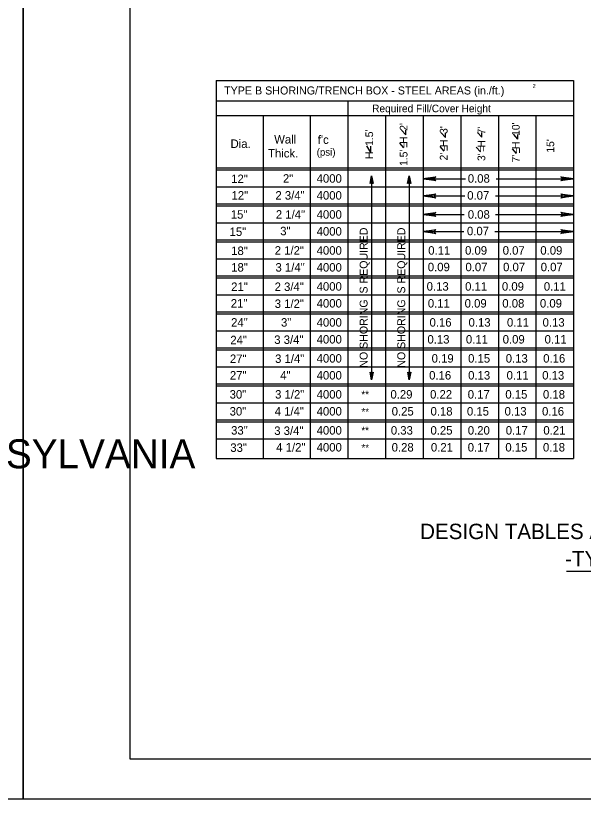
# Model space of a CAD drawing. Extents: x -22562 to -18409, y 3991 to 7171.
# Drawn here: x -20387.7 to -20175.1, y 3991.4 to 4284.9 of the extents above; entities that cross this region are included whole.
import ezdxf

# ---------------------------------------------------------------- set-up
doc = ezdxf.new("R2010")
doc.units = 0
for name, color, linetype in [('1', 7, 'Continuous'), ('2', 7, 'Continuous'), ('3', 7, 'Continuous'), ('4', 7, 'Continuous'), ('PLT-BNDY', 7, 'Continuous')]:
    doc.layers.add(name, color=color, linetype=linetype)

msp = doc.modelspace()

# ---------------------------------------------------------------- linework, layer by layer
at = {"layer": '1'}
for p, q in [((-20312.63, 4260.6), (-20312.63, 4119.05)), ((-20178.71, 4260.6), (-20178.71, 4119.05)), ((-20263.29, 4253.03), (-20263.29, 4119.05)), ((-20312.63, 4247.53), (-20178.71, 4247.53)), ((-20295.01, 4247.53), (-20295.01, 4119.05)), ((-20277.39, 4247.53), (-20277.39, 4119.05)), ((-20249.19, 4247.53), (-20249.19, 4119.05)), ((-20235.1, 4247.53), (-20235.1, 4119.05)), ((-20221, 4247.53), (-20221, 4119.05)), ((-20206.9, 4247.53), (-20206.9, 4119.05)), ((-20192.8, 4247.53), (-20192.8, 4119.05)), ((-20241.61, 4240.25), (-20243.17, 4242.01)), ((-20241.61, 4240.25), (-20241.61, 4242)), ((-20226.72, 4239.3), (-20228.28, 4241.07)), ((-20226.72, 4239.3), (-20226.72, 4241.06)), ((-20213.14, 4239.36), (-20214.7, 4241.13)), ((-20213.14, 4239.36), (-20213.14, 4241.12)), ((-20199.59, 4238.61), (-20201.15, 4240.38)), ((-20199.59, 4238.61), (-20199.59, 4240.37)), ((-20178.71, 4239.8), (-20178.71, 4119.27)), ((-20254.61, 4233.68), (-20256.17, 4236.11)), ((-20254.61, 4233.68), (-20254.61, 4236.09)), ((-20242.26, 4235.44), (-20243.83, 4237.21)), ((-20227.17, 4234.16), (-20228.73, 4235.93)), ((-20213.6, 4233.95), (-20215.16, 4235.71)), ((-20200.04, 4233.25), (-20201.61, 4235.02)), ((-20312.63, 4227.9), (-20178.71, 4227.9)), ((-20312.63, 4227.11), (-20178.71, 4227.11)), ((-20235.1, 4223.83), (-20219.22, 4223.83)), ((-20207.76, 4223.83), (-20178.71, 4223.83)), ((-20312.63, 4220.77), (-20178.71, 4220.77)), ((-20312.63, 4220.77), (-20178.71, 4220.77)), ((-20235.1, 4217.37), (-20219.43, 4217.37)), ((-20207.97, 4217.37), (-20178.71, 4217.37)), ((-20312.63, 4214.42), (-20178.71, 4214.42)), ((-20312.63, 4214.42), (-20178.71, 4214.42)), ((-20312.63, 4213.63), (-20178.71, 4213.63)), ((-20235.1, 4210.48), (-20219.64, 4210.48)), ((-20207.97, 4210.48), (-20178.71, 4210.48)), ((-20312.63, 4207.29), (-20178.71, 4207.29)), ((-20312.63, 4207.29), (-20178.71, 4207.29)), ((-20235.1, 4204.02), (-20219.85, 4204.02)), ((-20208.18, 4204.02), (-20178.71, 4204.02)), ((-20312.63, 4200.94), (-20178.71, 4200.94)), ((-20312.63, 4200.94), (-20178.71, 4200.94)), ((-20312.63, 4200.15), (-20178.71, 4200.15)), ((-20312.63, 4193.81), (-20178.71, 4193.81)), ((-20312.63, 4193.81), (-20178.71, 4193.81)), ((-20312.63, 4187.46), (-20178.71, 4187.46)), ((-20312.63, 4187.46), (-20178.71, 4187.46)), ((-20312.63, 4186.67), (-20178.71, 4186.67)), ((-20312.63, 4180.33), (-20178.71, 4180.33)), ((-20312.63, 4180.33), (-20178.71, 4180.33)), ((-20312.63, 4173.98), (-20178.71, 4173.98)), ((-20312.63, 4173.98), (-20178.71, 4173.98)), ((-20312.63, 4173.19), (-20178.71, 4173.19)), ((-20312.63, 4166.85), (-20178.71, 4166.85)), ((-20312.63, 4166.85), (-20178.71, 4166.85)), ((-20312.63, 4160.5), (-20178.71, 4160.5)), ((-20312.63, 4160.5), (-20178.71, 4160.5)), ((-20312.63, 4159.71), (-20178.71, 4159.71)), ((-20312.63, 4153.37), (-20178.71, 4153.37)), ((-20312.63, 4153.37), (-20178.71, 4153.37)), ((-20312.63, 4147.02), (-20178.71, 4147.02)), ((-20312.63, 4147.02), (-20178.71, 4147.02)), ((-20312.63, 4146.23), (-20178.71, 4146.23)), ((-20312.63, 4139.89), (-20178.71, 4139.89)), ((-20312.63, 4139.89), (-20178.71, 4139.89)), ((-20312.63, 4133.54), (-20178.71, 4133.54)), ((-20312.63, 4133.54), (-20178.71, 4133.54)), ((-20312.63, 4132.75), (-20178.71, 4132.75)), ((-20312.63, 4126.41), (-20178.71, 4126.41)), ((-20312.63, 4126.41), (-20178.71, 4126.41)), ((-20312.63, 4119.05), (-20178.71, 4119.05))]:
    msp.add_line(p, q, dxfattribs=at)
for points in [[(-20230.57, 4223.26), (-20230.74, 4223.59), (-20235.1, 4223.83), (-20230.57, 4223.26), (-20230.34, 4223.06), (-20235.1, 4223.83), (-20230.74, 4224.05), (-20230.58, 4224.37), (-20235.1, 4223.83), (-20230.34, 4224.59), (-20230.58, 4224.37)], [(-20183.23, 4224.4), (-20183.07, 4224.07), (-20178.71, 4223.83), (-20183.23, 4224.4), (-20183.47, 4224.6), (-20178.71, 4223.83), (-20183.06, 4223.62), (-20183.22, 4223.29), (-20178.71, 4223.83), (-20183.47, 4223.07), (-20183.22, 4223.29)], [(-20230.57, 4216.8), (-20230.74, 4217.13), (-20235.1, 4217.37), (-20230.57, 4216.8), (-20230.34, 4216.6), (-20235.1, 4217.37), (-20230.74, 4217.58), (-20230.58, 4217.9), (-20235.1, 4217.37), (-20230.34, 4218.12), (-20230.58, 4217.9)], [(-20183.23, 4217.93), (-20183.07, 4217.61), (-20178.71, 4217.37), (-20183.23, 4217.93), (-20183.47, 4218.13), (-20178.71, 4217.37), (-20183.06, 4217.15), (-20183.22, 4216.83), (-20178.71, 4217.37), (-20183.47, 4216.61), (-20183.22, 4216.83)], [(-20230.57, 4209.92), (-20230.74, 4210.24), (-20235.1, 4210.48), (-20230.57, 4209.92), (-20230.34, 4209.72), (-20235.1, 4210.48), (-20230.74, 4210.7), (-20230.58, 4211.02), (-20235.1, 4210.48), (-20230.34, 4211.24), (-20230.58, 4211.02)], [(-20183.23, 4211.05), (-20183.07, 4210.72), (-20178.71, 4210.48), (-20183.23, 4211.05), (-20183.47, 4211.25), (-20178.71, 4210.48), (-20183.06, 4210.27), (-20183.22, 4209.95), (-20178.71, 4210.48), (-20183.47, 4209.73), (-20183.22, 4209.95)], [(-20230.57, 4203.45), (-20230.74, 4203.78), (-20235.1, 4204.02), (-20230.57, 4203.45), (-20230.34, 4203.25), (-20235.1, 4204.02), (-20230.74, 4204.23), (-20230.58, 4204.55), (-20235.1, 4204.02), (-20230.34, 4204.77), (-20230.58, 4204.55)], [(-20183.23, 4204.58), (-20183.07, 4204.26), (-20178.71, 4204.02), (-20183.23, 4204.58), (-20183.47, 4204.78), (-20178.71, 4204.02), (-20183.06, 4203.8), (-20183.22, 4203.48), (-20178.71, 4204.02), (-20183.47, 4203.26), (-20183.22, 4203.48)]]:
    msp.add_lwpolyline(points, dxfattribs=at)
at = {"layer": '2'}
for p, q in [((-20344.85, 4006.37), (-20344.85, 4570.37)), ((-20312.63, 4260.6), (-20178.71, 4260.6)), ((-20312.63, 4253.03), (-20178.71, 4253.03)), ((-20254.4, 4224.92), (-20254.4, 4148.54)), ((-20240.3, 4224.92), (-20240.3, 4148.54)), ((-20181.42, 4076.88), (-19960.99, 4076.88)), ((-19558.85, 4006.37), (-20344.85, 4006.37))]:
    msp.add_line(p, q, dxfattribs=at)
for points in [[(-20254.82, 4222.2), (-20254.58, 4222.3), (-20254.4, 4224.92), (-20254.82, 4222.2), (-20254.97, 4222.06), (-20254.4, 4224.92), (-20254.24, 4222.3), (-20253.99, 4222.21), (-20254.4, 4224.92), (-20253.84, 4222.06), (-20253.99, 4222.21)], [(-20240.73, 4222.2), (-20240.48, 4222.3), (-20240.3, 4224.92), (-20240.73, 4222.2), (-20240.87, 4222.06), (-20240.3, 4224.92), (-20240.14, 4222.3), (-20239.9, 4222.21), (-20240.3, 4224.92), (-20239.74, 4222.06), (-20239.9, 4222.21)], [(-20253.97, 4151.26), (-20254.21, 4151.16), (-20254.4, 4148.54), (-20253.97, 4151.26), (-20253.83, 4151.4), (-20254.4, 4148.54), (-20254.56, 4151.15), (-20254.8, 4151.25), (-20254.4, 4148.54), (-20254.96, 4151.4), (-20254.8, 4151.25)], [(-20239.87, 4151.26), (-20240.12, 4151.16), (-20240.3, 4148.54), (-20239.87, 4151.26), (-20239.73, 4151.4), (-20240.3, 4148.54), (-20240.46, 4151.15), (-20240.71, 4151.25), (-20240.3, 4148.54), (-20240.86, 4151.4), (-20240.71, 4151.25)]]:
    msp.add_lwpolyline(points, dxfattribs=at)
at = {"layer": 'PLT-BNDY'}
for points in [[(-21225.85, 4585.37), (-20384.85, 4585.37), (-20384.85, 3991.37), (-21225.85, 3991.37)], [(-20384.85, 4585.37), (-19543.85, 4585.37), (-19543.85, 3991.37), (-20384.85, 3991.37)]]:
    msp.add_lwpolyline(points, close=True, dxfattribs=at)

# ---------------------------------------------------------------- texts
at = {"layer": '1'}
for s, height, p in [("f'c", 3.172, (-20274.54, 4236.87)), ('Thick.', 3.172, (-20293.17, 4231.79)), ('(psi)', 2.719, (-20274.95, 4232.46))]:
    msp.add_text(s, height=height, dxfattribs=at).set_placement(p)
for s, height, p in [('=', 2.88, (-20240.32, 4235.41)), ('=', 2.88, (-20225.22, 4234.13)), ('=', 2.88, (-20211.65, 4233.92)), ("15'", 2.883, (-20185.97, 4233.61)), ('=', 2.88, (-20198.1, 4233.22)), ('NO SHORING IS REQUIRED', 2.9685, (-20255.88, 4153.05)), ('NO SHORING IS REQUIRED', 2.9685, (-20241.78, 4153.05))]:
    msp.add_text(s, height=height, rotation=90, dxfattribs=at).set_placement(p)
at = {"layer": '2'}
for s, height, p in [('2', 1.5, (-20194.06, 4257.83)), ('TYPE B SHORING/TRENCH BOX - STEEL AREAS (in./ft.)', 3, (-20309.64, 4255.39)), ('Required Fill/Cover Height', 2.8357, (-20254.17, 4248.74)), ('Wall', 3.172, (-20290.87, 4237.01)), ('Dia.', 3.172, (-20307.21, 4235.37)), ('12"', 3.172, (-20306.98, 4222.22)), ('2"', 3.172, (-20287.59, 4222.35)), ('4000', 3.172, (-20274.96, 4222.35)), ('12"', 3.172, (-20306.84, 4216.01)), ('2 3/4"', 3.172, (-20290.41, 4216.01)), ('4000', 3.172, (-20274.96, 4216.01)), ('15"', 3.172, (-20307.13, 4208.87)), ('2 1/4"', 3.172, (-20290.24, 4208.87)), ('4000', 3.172, (-20274.96, 4208.87)), ('15"', 3.172, (-20307.56, 4202.4)), ('3"', 3.172, (-20288.6, 4202.66)), ('4000', 3.172, (-20274.96, 4202.53)), ('18"', 3.172, (-20306.98, 4195.26)), ('2 1/2"', 3.172, (-20290.67, 4195.39)), ('4000', 3.172, (-20274.96, 4195.39)), ('18"', 3.172, (-20306.98, 4189.05)), ('3 1/4"', 3.172, (-20290.38, 4189.05)), ('4000', 3.172, (-20274.96, 4189.05)), ('21"', 3.172, (-20306.98, 4181.79)), ('2 3/4"', 3.172, (-20290.7, 4181.79)), ('4000', 3.172, (-20274.96, 4181.91)), ('21"', 3.172, (-20307.13, 4175.57)), ('3 1/2"', 3.172, (-20290.67, 4175.44)), ('4000', 3.172, (-20274.96, 4175.57)), ('24"', 3.172, (-20307.01, 4168.43)), ('3"', 3.172, (-20288.31, 4168.43)), ('4000', 3.172, (-20274.96, 4168.43)), ('24"', 3.172, (-20307.3, 4161.83)), ('3 3/4"', 3.172, (-20290.84, 4161.96)), ('4000', 3.172, (-20274.96, 4162.09)), ('27"', 3.172, (-20307.45, 4154.82)), ('3 1/4"', 3.172, (-20290.53, 4154.83)), ('4000', 3.172, (-20274.96, 4154.95)), ('27"', 3.172, (-20307.45, 4148.61)), ('4"', 3.172, (-20288.6, 4148.61)), ('4000', 3.172, (-20274.96, 4148.61)), ('30"', 3.172, (-20307.55, 4141.47)), ('3 1/2"', 3.172, (-20290.53, 4141.47)), ('4000', 3.172, (-20274.96, 4141.47)), ('30"', 3.172, (-20307.55, 4135.13)), ('4 1/4"', 3.172, (-20290.67, 4135.13)), ('4000', 3.172, (-20274.96, 4135.13)), ('33"', 3.172, (-20307.01, 4127.99)), ('3 3/4"', 3.172, (-20290.84, 4127.86)), ('4000', 3.172, (-20274.96, 4127.99)), ('COMMONWEALTH OF PENNSYLVANIA', 10.8525, (-20588.1, 4115.37)), ('33"', 3.172, (-20307.3, 4121.52)), ('4 1/2"', 3.172, (-20290.1, 4121.65)), ('4000', 3.172, (-20274.96, 4121.65)), ('DESIGN TABLES AND PROOF TEST LOAD TABLE FOR CIRCULAR PIPES', 5.7669, (-20236.21, 4088.84)), ('-TYPE B SHORING/TRENCH BOX INSTALLATION', 5.7669, (-20181.88, 4078.62))]:
    msp.add_text(s, height=height, dxfattribs=at).set_placement(p)
at = {"layer": '3'}
for s, height, p in [('0.08', 3.172, (-20218.34, 4222.35)), ('0.07', 3.172, (-20218.55, 4216.01)), ('0.08', 3.172, (-20218.35, 4208.87)), ('0.07', 3.172, (-20218.65, 4202.66)), ('0.11', 3.172, (-20233.16, 4195.39)), ('0.09', 3.172, (-20219.37, 4195.39)), ('0.07', 3.172, (-20205.27, 4195.39)), ('0.09', 3.172, (-20191.17, 4195.39)), ('0.09', 3.172, (-20233.33, 4189.18)), ('0.07', 3.172, (-20219.22, 4189.18)), ('0.07', 3.172, (-20205.13, 4189.18)), ('0.07', 3.172, (-20191.03, 4189.18)), ('0.13', 3.172, (-20233.75, 4181.91)), ('0.11', 3.172, (-20219.34, 4181.91)), ('0.09', 3.172, (-20205.56, 4181.91)), ('0.11', 3.172, (-20189.86, 4181.91)), ('0.11', 3.172, (-20233.31, 4175.57)), ('0.09', 3.172, (-20219.52, 4175.57)), ('0.08', 3.172, (-20205.41, 4175.57)), ('0.09', 3.172, (-20191.32, 4175.57)), ('0.16', 3.172, (-20232.67, 4168.43)), ('0.13', 3.172, (-20218.06, 4168.43)), ('0.11', 3.172, (-20203.67, 4168.43)), ('0.13', 3.172, (-20190.32, 4168.43)), ('0.13', 3.172, (-20233.46, 4162.09)), ('0.11', 3.172, (-20219.05, 4162.09)), ('0.09', 3.172, (-20205.27, 4162.09)), ('0.11', 3.172, (-20189.57, 4162.09)), ('0.19', 3.172, (-20231.88, 4154.95)), ('0.15', 3.172, (-20218.23, 4154.95)), ('0.13', 3.172, (-20204.13, 4154.95)), ('0.16', 3.172, (-20190.09, 4154.95)), ('0.16', 3.172, (-20232.82, 4148.61)), ('0.13', 3.172, (-20218.21, 4148.61)), ('0.11', 3.172, (-20203.81, 4148.61)), ('0.13', 3.172, (-20190.46, 4148.61)), ('**', 2.753, (-20258.22, 4141.67)), ('0.29', 3.172, (-20247.32, 4141.47)), ('0.22', 3.172, (-20232.47, 4141.47)), ('0.17', 3.172, (-20218.37, 4141.47)), ('0.15', 3.172, (-20204.27, 4141.47)), ('0.18', 3.172, (-20190.18, 4141.47)), ('**', 2.753, (-20258.19, 4135.16)), ('0.25', 3.172, (-20246.85, 4135.13)), ('0.18', 3.172, (-20232.3, 4135.13)), ('0.15', 3.172, (-20218.66, 4135.13)), ('0.13', 3.172, (-20204.56, 4135.13)), ('0.16', 3.172, (-20190.53, 4135.13)), ('**', 2.753, (-20258.22, 4128.19)), ('0.33', 3.172, (-20247.17, 4127.99)), ('0.25', 3.172, (-20232.32, 4127.99)), ('0.20', 3.172, (-20218.34, 4127.99)), ('0.17', 3.172, (-20204.13, 4127.99)), ('0.21', 3.172, (-20190.03, 4127.99)), ('**', 2.753, (-20258.19, 4121.68)), ('0.28', 3.172, (-20246.86, 4121.65)), ('0.21', 3.172, (-20232.16, 4121.65)), ('0.17', 3.172, (-20218.37, 4121.65)), ('0.15', 3.172, (-20204.27, 4121.65)), ('0.18', 3.172, (-20190.18, 4121.65))]:
    msp.add_text(s, height=height, dxfattribs=at).set_placement(p)
at = {"layer": '4'}
for s, height, p in [("7'  H  10'", 2.883, (-20198.91, 4229.93)), ("H  1.5'", 2.883, (-20253.82, 4231.21)), ("1.5'  H  2'", 2.8834, (-20240.93, 4228.63)), ("2'  H  3'", 2.883, (-20225.93, 4230.69)), ("3'  H  7'", 2.883, (-20211.81, 4230.47))]:
    msp.add_text(s, height=height, rotation=90, dxfattribs=at).set_placement(p)

doc.saveas('drawing.dxf')
